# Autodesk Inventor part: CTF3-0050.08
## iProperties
Shininess: 64.0
Length Units: 11269
Angle Units: 11279
Time Units: 11290
Mass Units: 11283
Length Display Precision: 3
Angle Display Precision: 2
Compacted: True
Part Number: CTF3-0050.08
Document SubType Name: Modeling
Created: 2003-11
Designer: Lollo
Density: 0.0
Volumn: 0.0
Area: 0.0
PropertySet Name: Model Information
Control State: 0
Master: False
Checked Out: False
Author: Lollo
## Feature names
1. Estrusione1 [Extrusion]
2. Foro1 [Hole]
